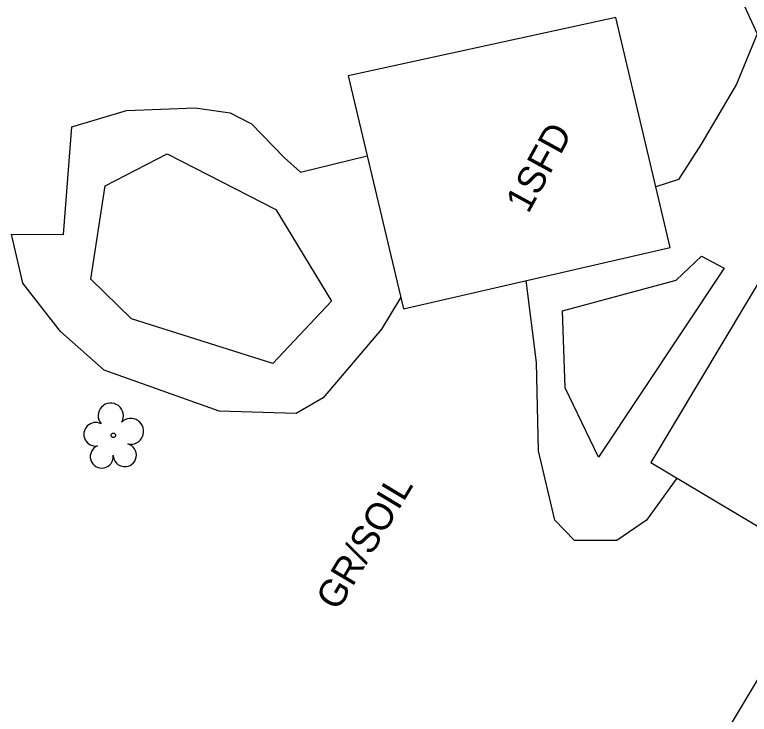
# Model space of a CAD drawing. Extents: x 553786 to 558838, y 502329 to 507342.
# Drawn here: x 557299.3 to 557407.1, y 506519.8 to 506622.5 of the extents above; entities that cross this region are included whole.
import ezdxf

# ---------------------------------------------------------------- set-up
doc = ezdxf.new("R2010")
doc.units = 0
for name, color, linetype in [('Exist Building Text', 7, 'Continuous'), ('Exist Roads Soil Text', 7, 'Continuous'), ('Exist Vegetation Tree CELL', 7, 'Continuous'), ('Exist Vegetation Woods Line', 7, 'Continuous'), ('Prop Drainage Structure Headwall CELL', 7, 'Continuous'), ('Prop Drainage Structure Pipe RCP 15in Class III Label', 7, 'Continuous'), ('Prop Drainage Structure Plot Symbol 50 Scale', 7, 'Continuous'), ('Prop Earthen Structure V Ditch Lateral Detail Label', 7, 'Continuous'), ('Prop Erosion Rip Rap Pad Outlet for Jurisdictional Stream CELL', 7, 'Continuous'), ('Sheet Layout Plan Border', 7, 'Continuous')]:
    doc.layers.add(name, color=color, linetype=linetype)

msp = doc.modelspace()

# ---------------------------------------------------------------- linework, layer by layer
at = {"layer": 'Exist Vegetation Tree CELL'}
msp.add_line((557313.78, 506560.71), (557313.78, 506560.71), dxfattribs=at)
msp.add_circle((557313.78, 506560.71), 0.326, dxfattribs=at)
for centre, radius, start, end in [((557313.4, 506563.58), 1.86, 330.1651, 219.7134), ((557316.33, 506561.3), 1.9, 257.1011, 134.1999), ((557311.18, 506560.86), 1.73, 62.6636, 279.3457), ((557312.08, 506557.59), 1.69, 111.5671, 6.231), ((557315.46, 506557.81), 1.7, 181.2822, 74.56)]:
    msp.add_arc(centre, radius, start, end, dxfattribs=at)
at = {"layer": 'Exist Vegetation Woods Line'}
msp.add_line((557400.08, 506587.03), (557403.43, 506585.27), dxfattribs=at)
for points in [[(557337.62, 506593.85), (557345.77, 506580.38), (557337.16, 506571.25), (557316.43, 506577.8), (557310.47, 506583.64), (557312.57, 506597.31), (557321.66, 506602.04), (557337.62, 506593.85)], [(557403.43, 506585.27), (557384.98, 506557.51), (557380.08, 506567.67), (557379.71, 506578.98), (557396.38, 506583.49), (557400.08, 506587.03)]]:
    msp.add_lwpolyline(points, dxfattribs=at)
at = {"layer": 'Prop Drainage Structure Headwall CELL'}
msp.add_spline([(557349.66, 506285.99), (557356.68, 506304.83), (557369.49, 506338.98), (557383.09, 506372.99), (557398.1, 506408.04), (557412.26, 506438.22), (557428.64, 506471.13), (557445.79, 506503.68), (557462.92, 506534.76), (557481.94, 506567.34), (557500.9, 506597.37), (557518.14, 506623.31), (557536.7, 506650.1), (557557.52, 506678.2), (557580.81, 506708.65), (557602.41, 506735.48)], degree=3, dxfattribs=at)
at = {"layer": 'Prop Drainage Structure Pipe RCP 15in Class III Label'}
msp.add_arc((558713.49, 505815.19), 1462.39, 142.91617, 158.42006, dxfattribs=at)
at = {"layer": 'Prop Drainage Structure Plot Symbol 50 Scale'}
msp.add_spline([(557546.82, 506691.06), (557545.79, 506691.27), (557542.77, 506691.81), (557539.62, 506691.56), (557529.48, 506689.45), (557518.91, 506687.16), (557485.73, 506679.35), (557450.97, 506671.07), (557428.25, 506665.66), (557416.71, 506663.04), (557384.25, 506655.82), (557350.02, 506647.96), (557314.55, 506639.92), (557294.97, 506635.34), (557286.93, 506633.6), (557278.79, 506631.78), (557245.32, 506624.15), (557211.96, 506616.3)], degree=3, dxfattribs=at)
at = {"layer": 'Prop Earthen Structure V Ditch Lateral Detail Label'}
for points in [[(557406.03, 506624.46), (557408.28, 506619.62), (557405.24, 506612.28), (557400.03, 506603.46), (557396.69, 506598.27), (557393.37, 506597.18)], [(557355.96, 506580.98), (557353.14, 506576.3), (557344.56, 506566.2), (557340.6, 506563.91), (557329.3, 506564.25), (557312.44, 506570.28), (557306.01, 506575.94), (557300.52, 506583.06), (557298.85, 506590.25), (557306.44, 506590.17), (557307.67, 506605.98), (557315.72, 506608.37), (557325.79, 506608.78), (557330.93, 506608.05), (557334.07, 506606.43), (557338.83, 506601.51), (557341.22, 506599.35), (557351.03, 506601.76)], [(557396.46, 506554.44), (557392.01, 506548.25), (557387.65, 506545.27), (557381.46, 506545.26), (557378.55, 506548.28), (557376.19, 506558.44), (557375.88, 506571.41), (557374.36, 506583.43)], [(557418.61, 506490.19), (557409.96, 506494.07), (557395.54, 506503.13), (557403.17, 506516.23), (557416.71, 506538.81), (557417.6, 506541.85)]]:
    msp.add_lwpolyline(points, dxfattribs=at)
at = {"layer": 'Prop Erosion Rip Rap Pad Outlet for Jurisdictional Stream CELL'}
for points in [[(557387.5, 506622.06), (557348.24, 506613.5), (557356.36, 506579.29), (557395.47, 506588.28)], [(557420.15, 506540.33), (557458.94, 506606.11), (557432.04, 506622.29), (557429.5, 506618.31), (557425.7, 506620.57), (557420.03, 506612.31), (557424.37, 506609.73), (557392.64, 506556.72)]]:
    msp.add_lwpolyline(points, close=True, dxfattribs=at)
at = {"layer": 'Sheet Layout Plan Border'}
msp.add_arc((558713.49, 505815.19), 1432.39, 139.65, 158.42006, dxfattribs=at)

# ---------------------------------------------------------------- texts
at = {"layer": 'Exist Building Text'}
msp.add_text('1SFD', height=4, rotation=61.3336, dxfattribs=at).set_placement((557374.66, 506593.13))
at = {"layer": 'Exist Roads Soil Text'}
msp.add_text('GR/SOIL', height=4, rotation=59.035, dxfattribs=at).set_placement((557346.72, 506534.79))

doc.saveas('drawing.dxf')
